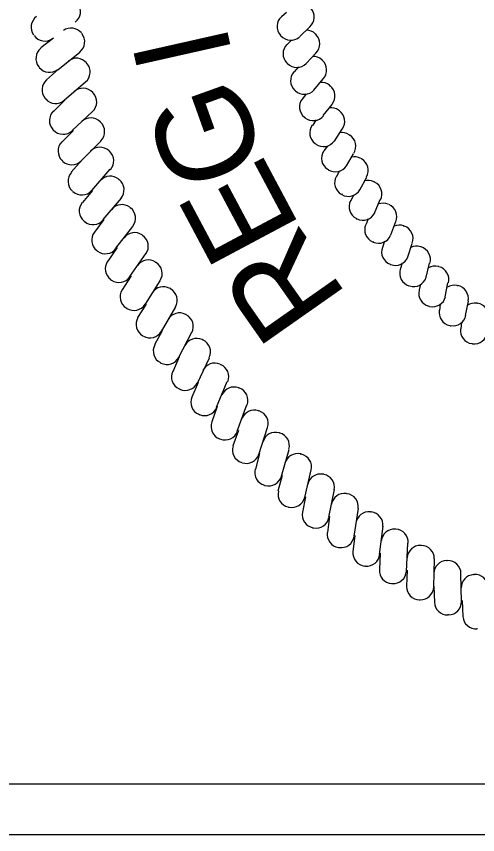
# Model space of a CAD drawing. Extents: x 1458004.1 to 1458040.9, y 194172.7 to 194198.1.
# Drawn here: x 1458037.569 to 1458038.114, y 194176.047 to 194177.014 of the extents above; entities that cross this region are included whole.
import ezdxf

# ---------------------------------------------------------------- set-up
doc = ezdxf.new("R2010")
doc.units = 0
for name, color, linetype in [('Eng_Stamp', 7, 'Continuous'), ('Eng_Stamp_Text_4', 7, 'Continuous'), ('Text_Box_4', 7, 'Continuous')]:
    doc.layers.add(name, color=color, linetype=linetype)

msp = doc.modelspace()

# ---------------------------------------------------------------- linework, layer by layer
at = {"layer": 'Eng_Stamp'}
for p, q in [((1458037.88833, 194177.01833), (1458037.8825, 194177.01333)), ((1458037.90417, 194176.99), (1458037.91583, 194177.00167)), ((1458037.59, 194176.99167), (1458037.59, 194176.99167)), ((1458037.61333, 194176.98833), (1458037.59833, 194176.97667)), ((1458037.88083, 194176.99167), (1458037.88167, 194176.99083)), ((1458037.89417, 194176.98583), (1458037.88917, 194176.98083)), ((1458037.92333, 194176.9925), (1458037.9225, 194176.99333)), ((1458037.61833, 194176.95083), (1458037.64417, 194176.97167)), ((1458037.91167, 194176.95833), (1458037.92333, 194176.97083)), ((1458037.6525, 194176.95833), (1458037.65167, 194176.95917)), ((1458037.88917, 194176.95833), (1458037.89, 194176.95833)), ((1458037.93083, 194176.9625), (1458037.93, 194176.9625)), ((1458037.59583, 194176.95417), (1458037.59667, 194176.95417)), ((1458037.61917, 194176.95167), (1458037.605, 194176.93917)), ((1458037.9025, 194176.95417), (1458037.8975, 194176.94833)), ((1458037.62583, 194176.915), (1458037.65083, 194176.93667)), ((1458037.92083, 194176.92667), (1458037.93167, 194176.94)), ((1458037.94, 194176.93167), (1458037.93917, 194176.9325)), ((1458037.66, 194176.92333), (1458037.65917, 194176.92417)), ((1458037.89833, 194176.92667), (1458037.89917, 194176.92583)), ((1458037.91167, 194176.9225), (1458037.9075, 194176.91667)), ((1458037.60333, 194176.91667), (1458037.60417, 194176.91667)), ((1458037.62667, 194176.915), (1458037.61333, 194176.90167)), ((1458037.93167, 194176.89667), (1458037.9425, 194176.91)), ((1458037.635, 194176.87917), (1458037.65917, 194176.90167)), ((1458037.95083, 194176.9025), (1458037.95, 194176.90333)), ((1458037.66917, 194176.88917), (1458037.66833, 194176.88917)), ((1458037.91, 194176.895), (1458037.91, 194176.89417)), ((1458037.92333, 194176.89167), (1458037.91917, 194176.885)), ((1458037.6125, 194176.88), (1458037.61333, 194176.87917)), ((1458037.63667, 194176.87917), (1458037.62333, 194176.86583)), ((1458037.945, 194176.86667), (1458037.95417, 194176.88083)), ((1458037.96333, 194176.87333), (1458037.9625, 194176.87417)), ((1458037.64583, 194176.84333), (1458037.66917, 194176.86667)), ((1458037.9225, 194176.86333), (1458037.92333, 194176.86333)), ((1458037.93667, 194176.86083), (1458037.9325, 194176.855)), ((1458037.67917, 194176.855), (1458037.67833, 194176.855)), ((1458037.95917, 194176.8375), (1458037.9675, 194176.85167)), ((1458037.62333, 194176.84417), (1458037.62417, 194176.84333)), ((1458037.64667, 194176.84417), (1458037.63417, 194176.83)), ((1458037.9775, 194176.84583), (1458037.97667, 194176.84583)), ((1458037.65833, 194176.80833), (1458037.68, 194176.83333)), ((1458037.9375, 194176.83333), (1458037.9375, 194176.8325)), ((1458037.95083, 194176.83167), (1458037.9475, 194176.825)), ((1458037.69083, 194176.82083), (1458037.69, 194176.82167)), ((1458037.975, 194176.80917), (1458037.98333, 194176.82417)), ((1458037.9925, 194176.81833), (1458037.99167, 194176.81833)), ((1458037.63583, 194176.8075), (1458037.63583, 194176.8075)), ((1458037.65917, 194176.80833), (1458037.6475, 194176.79417)), ((1458037.95333, 194176.80417), (1458037.95417, 194176.80333)), ((1458037.9675, 194176.8025), (1458037.96417, 194176.79583)), ((1458037.67167, 194176.77417), (1458037.69333, 194176.79917)), ((1458037.9925, 194176.78167), (1458037.99917, 194176.7975)), ((1458038.00917, 194176.79167), (1458038.00917, 194176.79167)), ((1458037.70417, 194176.7875), (1458037.70333, 194176.78833)), ((1458037.64917, 194176.7725), (1458037.65, 194176.77167)), ((1458037.6725, 194176.77417), (1458037.66167, 194176.75917)), ((1458037.97083, 194176.775), (1458037.97167, 194176.775)), ((1458037.985, 194176.775), (1458037.9825, 194176.76833)), ((1458037.68667, 194176.74), (1458037.70667, 194176.76583)), ((1458038.01167, 194176.75583), (1458038.0175, 194176.77167)), ((1458038.0275, 194176.76583), (1458038.02667, 194176.76667)), ((1458037.71833, 194176.755), (1458037.71833, 194176.75583)), ((1458037.99, 194176.7475), (1458037.99167, 194176.7475)), ((1458038.00417, 194176.74833), (1458038.00167, 194176.74083)), ((1458038.03167, 194176.73), (1458038.03667, 194176.74583)), ((1458037.66417, 194176.7375), (1458037.665, 194176.73667)), ((1458037.68833, 194176.74083), (1458037.6775, 194176.725)), ((1458037.70333, 194176.70667), (1458037.7225, 194176.73417)), ((1458038.0475, 194176.74167), (1458038.04667, 194176.74167)), ((1458037.73417, 194176.72333), (1458037.73333, 194176.72333)), ((1458038.01083, 194176.72083), (1458038.01167, 194176.72083)), ((1458038.025, 194176.7225), (1458038.0225, 194176.715)), ((1458038.05333, 194176.70583), (1458038.0575, 194176.7225)), ((1458038.06833, 194176.71833), (1458038.0675, 194176.71833)), ((1458037.705, 194176.7075), (1458037.69417, 194176.69083)), ((1458037.68083, 194176.7025), (1458037.68167, 194176.7025)), ((1458037.72167, 194176.67417), (1458037.73917, 194176.70167)), ((1458038.03333, 194176.69583), (1458038.03333, 194176.69583)), ((1458038.04667, 194176.6975), (1458038.045, 194176.69083)), ((1458038.07583, 194176.6825), (1458038.07917, 194176.69917)), ((1458038.09083, 194176.69583), (1458038.09, 194176.69583)), ((1458037.75167, 194176.6925), (1458037.75083, 194176.6925)), ((1458038.1, 194176.66083), (1458038.10333, 194176.6775)), ((1458037.69917, 194176.66917), (1458037.7, 194176.66917)), ((1458037.7225, 194176.67417), (1458037.7125, 194176.65833)), ((1458037.74083, 194176.64167), (1458037.7575, 194176.67083)), ((1458038.05667, 194176.67167), (1458038.0575, 194176.67167)), ((1458038.07, 194176.67417), (1458038.06917, 194176.66667)), ((1458038.11417, 194176.675), (1458038.11333, 194176.675)), ((1458037.77, 194176.66167), (1458037.76917, 194176.66167)), ((1458038.08167, 194176.64833), (1458038.0825, 194176.64833)), ((1458038.095, 194176.6525), (1458038.09417, 194176.645)), ((1458037.74167, 194176.6425), (1458037.7325, 194176.62583)), ((1458037.76083, 194176.61083), (1458037.77667, 194176.64083)), ((1458037.71833, 194176.63667), (1458037.71917, 194176.63667)), ((1458037.79, 194176.63167), (1458037.78917, 194176.6325)), ((1458038.1075, 194176.6275), (1458038.10833, 194176.6275)), ((1458037.76167, 194176.61167), (1458037.75417, 194176.59417)), ((1458037.78333, 194176.58083), (1458037.7975, 194176.61083)), ((1458037.73917, 194176.605), (1458037.74, 194176.60417)), ((1458037.81083, 194176.6025), (1458037.81, 194176.60333)), ((1458037.78417, 194176.58167), (1458037.77667, 194176.56417)), ((1458037.80583, 194176.5525), (1458037.81833, 194176.5825)), ((1458037.76167, 194176.57417), (1458037.7625, 194176.57417)), ((1458037.8325, 194176.575), (1458037.83167, 194176.575)), ((1458037.80667, 194176.55333), (1458037.8, 194176.535)), ((1458037.83, 194176.52417), (1458037.84167, 194176.555)), ((1458037.785, 194176.54417), (1458037.78583, 194176.54333)), ((1458037.85583, 194176.5475), (1458037.855, 194176.54833)), ((1458037.83167, 194176.525), (1458037.825, 194176.50667)), ((1458037.85583, 194176.49667), (1458037.86583, 194176.52833)), ((1458037.88083, 194176.52167), (1458037.88, 194176.5225)), ((1458037.80917, 194176.515), (1458037.81, 194176.515)), ((1458037.8825, 194176.47083), (1458037.89167, 194176.5025)), ((1458037.85667, 194176.4975), (1458037.85167, 194176.47917)), ((1458037.90583, 194176.49667), (1458037.905, 194176.4975)), ((1458037.835, 194176.4875), (1458037.83583, 194176.48667)), ((1458037.91, 194176.44583), (1458037.9175, 194176.47833)), ((1458037.9325, 194176.47333), (1458037.93167, 194176.47333)), ((1458037.88333, 194176.47167), (1458037.87833, 194176.45333)), ((1458037.8625, 194176.46), (1458037.86333, 194176.46)), ((1458037.93833, 194176.4225), (1458037.945, 194176.455)), ((1458037.91083, 194176.44667), (1458037.9075, 194176.42833)), ((1458037.96, 194176.45), (1458037.95917, 194176.45)), ((1458037.89083, 194176.43417), (1458037.89167, 194176.43417)), ((1458037.96833, 194176.4), (1458037.97333, 194176.4325)), ((1458037.98833, 194176.42833), (1458037.9875, 194176.42833)), ((1458037.93917, 194176.42333), (1458037.93667, 194176.40417)), ((1458037.91917, 194176.41), (1458037.92, 194176.41)), ((1458037.99833, 194176.37833), (1458038.0025, 194176.41167)), ((1458038.0175, 194176.40833), (1458038.01667, 194176.40833)), ((1458037.96917, 194176.40083), (1458037.96667, 194176.38167)), ((1458037.95, 194176.38667), (1458037.95083, 194176.38667)), ((1458038.03, 194176.35833), (1458038.03167, 194176.39167)), ((1458038.0475, 194176.38917), (1458038.04667, 194176.38917)), ((1458037.99917, 194176.38), (1458037.99833, 194176.36083)), ((1458038.0625, 194176.34), (1458038.06333, 194176.37333)), ((1458038.07833, 194176.37083), (1458038.0775, 194176.37083)), ((1458037.98083, 194176.365), (1458037.98167, 194176.365)), ((1458038.03083, 194176.36), (1458038.03, 194176.34083)), ((1458038.095, 194176.3225), (1458038.09417, 194176.35583)), ((1458038.11, 194176.35417), (1458038.10917, 194176.35417)), ((1458038.0125, 194176.34417), (1458038.01333, 194176.34417)), ((1458038.0625, 194176.34083), (1458038.06333, 194176.32167)), ((1458038.045, 194176.325), (1458038.04583, 194176.325)), ((1458038.09583, 194176.32417), (1458038.09667, 194176.305)), ((1458038.07917, 194176.3075), (1458038.08, 194176.3075)), ((1458038.11333, 194176.29083), (1458038.11417, 194176.29083))]:
    msp.add_line(p, q, dxfattribs=at)
for centre, start, end in [((1458037.62963, 194177.01987), 306, 36), ((1458037.90555, 194177.0131), 311.86692, 41.86692), ((1458037.60229, 194177.00113), 126, 216), ((1458037.8928, 194177.00196), 131.86692, 221.86692), ((1458037.63394, 194176.98463), 38.4, 125.78537), ((1458037.91143, 194176.98224), 44.97032, 88.00239), ((1458037.6028, 194177.00042), 216, 306), ((1458037.63447, 194176.98395), 308.4, 38.4), ((1458037.89338, 194177.00132), 221.86692, 311.86692), ((1458037.91204, 194176.98162), 314.97032, 44.97032), ((1458037.60795, 194176.96407), 128.4, 218.4), ((1458037.89991, 194176.96981), 134.97032, 224.97032), ((1458037.91958, 194176.95112), 48.07372, 91.10579), ((1458037.64025, 194176.94891), 40.8, 128.18537), ((1458037.64082, 194176.94826), 310.8, 40.8), ((1458037.90052, 194176.96919), 224.97032, 314.97032), ((1458037.92023, 194176.95054), 318.07372, 48.07372), ((1458037.60848, 194176.96339), 218.4, 308.4), ((1458037.90876, 194176.93809), 138.07372, 228.07372), ((1458037.61514, 194176.92729), 130.8, 220.8), ((1458037.64806, 194176.91349), 43.2, 130.58537), ((1458037.9094, 194176.93751), 228.07372, 318.07372), ((1458037.92941, 194176.92049), 51.17712, 94.20919), ((1458037.93008, 194176.91995), 321.17712, 51.17712), ((1458037.64865, 194176.91286), 313.2, 43.2), ((1458037.61571, 194176.92663), 220.8, 310.8), ((1458037.9193, 194176.90689), 141.17712, 231.17712), ((1458037.62388, 194176.89084), 133.2, 223.2), ((1458037.94088, 194176.89044), 54.28052, 97.31259), ((1458037.94158, 194176.88993), 324.28052, 54.28052), ((1458037.65734, 194176.87843), 45.6, 132.98538), ((1458037.65796, 194176.87783), 315.6, 45.6), ((1458037.91998, 194176.90635), 231.17712, 321.17712), ((1458037.62447, 194176.89021), 223.2, 313.2), ((1458037.93152, 194176.87631), 144.28052, 234.28052), ((1458037.95396, 194176.86105), 57.38392, 100.41599), ((1458037.95469, 194176.86058), 327.38392, 57.38392), ((1458037.63413, 194176.85479), 135.6, 225.6), ((1458037.66808, 194176.84379), 48, 135.38538), ((1458037.93223, 194176.8758), 234.28052, 324.28052), ((1458037.66872, 194176.84321), 318, 48), ((1458037.94538, 194176.84644), 147.38392, 237.38392), ((1458037.63475, 194176.85418), 225.6, 315.6), ((1458037.96861, 194176.83242), 60.48732, 103.51939), ((1458037.96936, 194176.83199), 330.48732, 60.48732), ((1458037.94611, 194176.84597), 237.38392, 327.38392), ((1458037.64588, 194176.81919), 138, 228), ((1458037.68026, 194176.80963), 50.4, 137.78537), ((1458037.68093, 194176.80908), 320.4, 50.4), ((1458037.96084, 194176.81736), 150.48732, 240.48732), ((1458037.98479, 194176.80461), 63.59072, 106.62279), ((1458037.98556, 194176.80423), 333.59072, 63.59072), ((1458037.64652, 194176.81861), 228, 318), ((1458037.96159, 194176.81693), 240.48732, 330.48732), ((1458037.65911, 194176.78413), 140.4, 230.4), ((1458037.69386, 194176.77601), 52.8, 140.18537), ((1458037.97784, 194176.78916), 153.59072, 243.59072), ((1458038.00245, 194176.77773), 66.69412, 109.72619), ((1458038.00324, 194176.77739), 336.69412, 66.69412), ((1458037.69455, 194176.77549), 322.8, 52.8), ((1458037.97862, 194176.78877), 243.59072, 333.59072), ((1458037.65978, 194176.78357), 230.4, 320.4), ((1458037.99635, 194176.76192), 156.69412, 246.69412), ((1458038.02154, 194176.75184), 69.79752, 112.82959), ((1458038.02235, 194176.75154), 339.79752, 69.79752), ((1458037.6738, 194176.74964), 142.8, 232.8), ((1458037.70886, 194176.74299), 55.2, 142.58538), ((1458037.70957, 194176.7425), 325.2, 55.2), ((1458037.99715, 194176.76158), 246.69412, 336.69412), ((1458037.67449, 194176.74912), 232.8, 322.8), ((1458038.01631, 194176.73572), 159.79752, 249.79752), ((1458038.042, 194176.72702), 72.90092, 115.93299), ((1458038.04283, 194176.72677), 342.90092, 72.90092), ((1458037.68992, 194176.7158), 145.2, 235.2), ((1458037.72523, 194176.71063), 57.6, 144.98538), ((1458038.01712, 194176.73543), 249.79752, 339.79752), ((1458037.72596, 194176.71016), 327.6, 57.6), ((1458038.03765, 194176.71065), 162.90092, 252.90092), ((1458038.06378, 194176.70335), 76.00432, 119.03639), ((1458038.06462, 194176.70314), 346.00432, 76.00432), ((1458037.69063, 194176.71531), 235.2, 325.2), ((1458038.03848, 194176.71039), 252.90092, 342.90092), ((1458038.08681, 194176.68089), 79.10772, 122.13979), ((1458038.08766, 194176.68073), 349.10772, 79.10772), ((1458037.70745, 194176.68267), 147.6, 237.6), ((1458037.74294, 194176.67898), 60, 147.38538), ((1458037.74369, 194176.67855), 330, 60), ((1458038.06032, 194176.68676), 166.00432, 256.00432), ((1458038.06116, 194176.68655), 256.00432, 346.00432), ((1458037.70818, 194176.68221), 237.6, 327.6), ((1458038.08425, 194176.66414), 169.10772, 259.10772), ((1458038.11102, 194176.65971), 82.21112, 125.24319), ((1458038.11188, 194176.65959), 352.21112, 82.21112), ((1458037.72634, 194176.6503), 150, 240), ((1458037.76196, 194176.6481), 62.4, 149.78537), ((1458037.76273, 194176.6477), 332.4, 62.4), ((1458038.0851, 194176.66398), 259.10772, 349.10772), ((1458037.72709, 194176.64987), 240, 330), ((1458038.10937, 194176.64285), 172.21112, 262.21112), ((1458038.11023, 194176.64273), 262.21112, 352.21112), ((1458037.78225, 194176.61804), 64.8, 152.18537), ((1458037.78304, 194176.61767), 334.8, 64.8), ((1458037.74658, 194176.61875), 152.4, 242.4), ((1458037.74734, 194176.61835), 242.4, 332.4), ((1458037.80379, 194176.58886), 67.2, 154.58537), ((1458037.80459, 194176.58852), 337.2, 67.2), ((1458037.76811, 194176.58807), 154.8, 244.8), ((1458037.7689, 194176.58771), 244.8, 334.8), ((1458037.82653, 194176.5606), 69.6, 156.98538), ((1458037.82734, 194176.5603), 339.6, 69.6), ((1458037.79092, 194176.55833), 157.2, 247.2), ((1458037.79171, 194176.55799), 247.2, 337.2), ((1458037.85043, 194176.53333), 72, 159.38537), ((1458037.85125, 194176.53306), 342, 72), ((1458037.81495, 194176.52956), 159.6, 249.6), ((1458037.81576, 194176.52926), 249.6, 339.6), ((1458037.87545, 194176.50708), 74.4, 161.78538), ((1458037.87629, 194176.50684), 344.4, 74.4), ((1458037.84016, 194176.50183), 162, 252), ((1458037.84098, 194176.50156), 252, 342), ((1458037.90156, 194176.4819), 76.8, 164.18538), ((1458037.9024, 194176.4817), 346.8, 76.8), ((1458037.86651, 194176.47517), 164.4, 254.4), ((1458037.92869, 194176.45783), 79.2, 166.58537), ((1458037.92954, 194176.45767), 349.2, 79.2), ((1458037.86734, 194176.47494), 254.4, 344.4), ((1458037.89396, 194176.44964), 166.8, 256.8), ((1458037.8948, 194176.44945), 256.8, 346.8), ((1458037.9568, 194176.43492), 81.6, 168.98538), ((1458037.95766, 194176.43479), 351.6, 81.6), ((1458037.92244, 194176.42529), 169.2, 259.2), ((1458037.98586, 194176.41321), 84, 171.38538), ((1458037.98672, 194176.41312), 354, 84), ((1458037.9233, 194176.42513), 259.2, 349.2), ((1458038.01579, 194176.39273), 86.4, 173.78538), ((1458038.01666, 194176.39268), 356.4, 86.4), ((1458037.95193, 194176.40215), 171.6, 261.6), ((1458037.95279, 194176.40202), 261.6, 351.6), ((1458038.04656, 194176.37353), 88.8, 176.18537), ((1458038.04742, 194176.37351), 358.8, 88.8), ((1458037.98236, 194176.38026), 174, 264), ((1458037.98322, 194176.38017), 264, 354), ((1458038.0781, 194176.35563), 91.2, 178.58538), ((1458038.07897, 194176.35565), 1.2, 91.2), ((1458038.01368, 194176.35967), 176.4, 266.4), ((1458038.01454, 194176.35961), 266.4, 356.4), ((1458038.11037, 194176.33907), 93.6, 180.98537), ((1458038.11123, 194176.33912), 3.6, 93.6), ((1458038.04583, 194176.3404), 178.8, 268.8), ((1458038.04669, 194176.34039), 268.8, 358.8), ((1458038.07876, 194176.3225), 181.2, 271.2), ((1458038.07962, 194176.32252), 271.2, 1.2), ((1458038.11241, 194176.306), 183.6, 273.6)]:
    msp.add_arc(centre, 0.01558, start, end, dxfattribs=at)
at = {"layer": 'Text_Box_4'}
for p, q in [((1458032.09667, 194176.1075), (1458039.4, 194176.1075)), ((1458035.87833, 194176.0475), (1458039.4, 194176.0475))]:
    msp.add_line(p, q, dxfattribs=at)

# ---------------------------------------------------------------- texts
at = {"layer": 'Eng_Stamp_Text_4'}
for s, height, rotation, p in [('I', 0.11367, 102.68858, (1458037.825, 194176.9675)), ('G', 0.11367, 109.71152, (1458037.86583, 194176.8375)), ('E', 0.11367, 118.05427, (1458037.90583, 194176.76333)), ('R', 0.11368, 125.05162, (1458037.96167, 194176.6825))]:
    msp.add_text(s, height=height, rotation=rotation, dxfattribs=at).set_placement(p)

doc.saveas('drawing.dxf')
